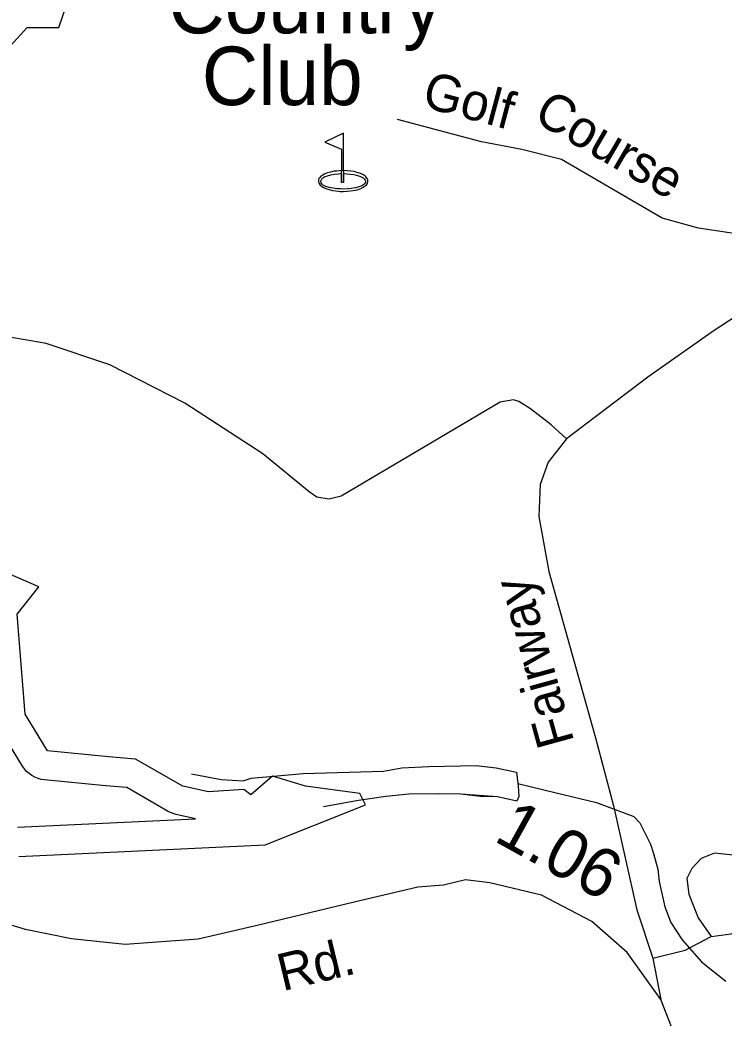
# Model space of a CAD drawing. Extents: x 1473865 to 1648260, y 639067 to 773536.
# Drawn here: x 1511554 to 1513360, y 649038 to 651596 of the extents above; entities that cross this region are included whole.
import ezdxf

# ---------------------------------------------------------------- set-up
doc = ezdxf.new("R2010")
doc.units = 0
for name, color, linetype in [('Exist Cultural Recreational Golf Course CELL', 7, 'Continuous'), ('Exist Hydrographic Buffer Line', 7, 'Continuous'), ('Exist Hydrographic Lake Shore', 7, 'Continuous'), ('Exist Hydrographic Misc Water Feature', 7, 'Continuous'), ('Exist Road Non-System Type 51', 7, 'Continuous'), ('Exist Road Non-System Type 51 Label', 7, 'Continuous'), ('Exist Road Secondary Mileage Hundredths English Label', 7, 'Continuous'), ('Exist Road Secondary Type 51 Attributed', 7, 'Continuous'), ('Exist Road Secondary Type 51 Label', 7, 'Continuous')]:
    doc.layers.add(name, color=color, linetype=linetype)

msp = doc.modelspace()

# ---------------------------------------------------------------- linework, layer by layer
at = {"layer": 'Exist Cultural Recreational Golf Course CELL'}
msp.add_lwpolyline([(1512384.3, 651305.8), (1512336, 651283.4), (1512378.7, 651264.7), (1512378.7, 651210.1), (1512384.3, 651210.1), (1512384.3, 651202.5), (1512384.3, 651179.6), (1512384.3, 651202.5), (1512391.5, 651202), (1512400.8, 651201), (1512410.4, 651199.8), (1512416.9, 651198.5), (1512425.4, 651196), (1512427.5, 651195.3), (1512434.4, 651191.7), (1512438.1, 651188.4), (1512439.7, 651185.5), (1512440.7, 651182.6), (1512440.6, 651181.2), (1512440.2, 651180), (1512439.9, 651179), (1512439.3, 651177.8), (1512436, 651174.2), (1512431.2, 651171.3), (1512422.9, 651168.1), (1512414.8, 651165.9), (1512404, 651164.2), (1512395.7, 651163), (1512383.5, 651162.4), (1512376.6, 651163), (1512367.8, 651163.4), (1512357.7, 651164.8), (1512347.3, 651167.1), (1512338.5, 651169.7), (1512332.5, 651172.3), (1512328.9, 651175.2), (1512326.3, 651178.8), (1512325.5, 651181.9), (1512326.3, 651185.2), (1512328.4, 651188.6), (1512331, 651191.5), (1512333.8, 651193.1), (1512337.3, 651194.9), (1512343.1, 651196.8), (1512351.1, 651199), (1512361.1, 651200.8), (1512370.8, 651202), (1512378.7, 651202.5), (1512378.7, 651210.1), (1512384.3, 651210.1), (1512384.3, 651179.6), (1512378.7, 651179.6), (1512378.7, 651202.5), (1512378.7, 651210.1), (1512366.4, 651209), (1512360.4, 651208.5), (1512351, 651206.3), (1512343.3, 651204.4), (1512334.6, 651201), (1512330.9, 651198.8), (1512326.1, 651195.8), (1512322.9, 651192.5), (1512321, 651190), (1512319.8, 651186.2), (1512319.5, 651183.3), (1512320.3, 651178.8), (1512321.2, 651176.7), (1512323.9, 651173), (1512326.4, 651170.8), (1512330.7, 651167.9), (1512334.3, 651166.1), (1512341.1, 651163.2), (1512346.8, 651161.7), (1512356.1, 651159.5), (1512364.6, 651157.8), (1512375.7, 651156.8), (1512382.9, 651156.5), (1512393.2, 651157.1), (1512400.9, 651157.8), (1512409, 651159.3), (1512418.7, 651161.2), (1512428.2, 651164.4), (1512434.1, 651167.5), (1512439.7, 651170.9), (1512442.7, 651173.9), (1512444.5, 651176.5), (1512445.3, 651178.1), (1512445.8, 651179.4), (1512446.2, 651181.3), (1512446.5, 651183.4), (1512446, 651186.8), (1512444.6, 651190), (1512441.6, 651193.8), (1512439.7, 651195.9), (1512435.2, 651198.9), (1512431.6, 651200.9), (1512425.3, 651203.5), (1512420.9, 651204.7), (1512410.9, 651207.4), (1512402.5, 651208.9), (1512384.3, 651210.1)], close=True, dxfattribs=at)
at = {"layer": 'Exist Hydrographic Buffer Line'}
msp.add_lwpolyline([(1511547.9, 649526.9), (1512004.2, 649548.1), (1511955.1, 649559.3), (1511944.5, 649562.6), (1511934.4, 649567.4), (1511828.1, 649628.5), (1511774.8, 649633.1), (1511774.4, 649633.1), (1511774, 649633.2), (1511617.7, 649648.3), (1511609.1, 649649.6), (1511600.8, 649651.9), (1511592.7, 649655.1), (1511585.1, 649659.3), (1511578.1, 649664.3), (1511571.6, 649670.1), (1511565.9, 649676.6), (1511560.9, 649683.7), (1511503.6, 649777.2)], dxfattribs=at)
at = {"layer": 'Exist Hydrographic Lake Shore'}
for points in [[(1511441, 651433.5), (1511573.3, 651577), (1511654.1, 651577), (1511694.5, 651694.7)], [(1511551.3, 649452), (1512183.4, 649481.4), (1512440.6, 649584.4), (1512425.9, 649613.8), (1512286.3, 649632.2), (1512201.7, 649657.9), (1512146.6, 649610.1), (1512128.6, 649623.4), (1512038.1, 649617.3), (1511971.8, 649632.4), (1511851.1, 649701.8), (1511781.2, 649707.8), (1511624.9, 649722.9), (1511567.6, 649816.4), (1511547.7, 650073.5), (1511602.8, 650143.4), (1511518.3, 650180.1)]]:
    msp.add_lwpolyline(points, dxfattribs=at)
at = {"layer": 'Exist Hydrographic Misc Water Feature'}
for points in [[(1511994.5, 649663.7), (1512070.3, 649649.5), (1512127.1, 649645.9), (1512147.1, 649652.8), (1512280.7, 649664.8), (1512486.1, 649670.3), (1512533.3, 649679.2), (1512602.6, 649682.7), (1512723.9, 649685), (1512775.6, 649679), (1512827.3, 649668), (1512830.9, 649639)], [(1512830.9, 649639), (1512831.6, 649633.3), (1512833.5, 649606.1), (1512828.3, 649593.8), (1512779, 649604.7), (1512734.5, 649605.7), (1512685.2, 649611.7), (1512630.9, 649612.8), (1512551.7, 649612.1), (1512492.3, 649605.9), (1512422.7, 649595.1), (1512332.9, 649579.5)], [(1512830.9, 649639), (1512831.6, 649633.3), (1512833.5, 649606.1), (1512828.3, 649593.8), (1512779, 649604.7), (1512685.2, 649611.7), (1512630.9, 649612.8), (1512551.7, 649612.1), (1512492.3, 649605.9), (1512422.7, 649595.1), (1512332.9, 649579.5)], [(1512830.9, 649639), (1512925.4, 649616.3), (1513033, 649590.3), (1513128.2, 649554.5), (1513144, 649538.2), (1513171, 649483.8), (1513178.6, 649459.6), (1513189.8, 649419.4), (1513193.2, 649387.4), (1513208.1, 649323.2), (1513223.4, 649282.9), (1513252.5, 649238.4), (1513301.5, 649181.5), (1513364.6, 649132.4)]]:
    msp.add_lwpolyline(points, dxfattribs=at)
at = {"layer": 'Exist Road Non-System Type 51'}
for p, q in [((1512737.6, 651283.5), (1512522.6, 651340.9)), ((1513177.3, 649191.6), (1513197.9, 649085.4))]:
    msp.add_line(p, q, dxfattribs=at)
for points in [[(1513640.8, 650977.3), (1513553.4, 651006.7), (1513407.9, 651045.1), (1513294.2, 651062.8), (1513200.6, 651088.3), (1512942.9, 651238.3), (1512841.4, 651263.8), (1512737.6, 651283.5)], [(1513640.8, 650977.3), (1513532.2, 650929.1), (1513334.1, 650800.2), (1513164.2, 650680.8), (1512955.9, 650522.1)], [(1512955.9, 650522.1), (1512916.4, 650558.7), (1512863, 650599.6), (1512833.4, 650618), (1512819.5, 650622.3), (1512785.3, 650616.8), (1512377.7, 650375.3), (1512347.5, 650367.9), (1512315.8, 650373.3), (1512295.9, 650386.5), (1512177.4, 650484.4), (1511977.3, 650613.7), (1511784.8, 650712.6), (1511621.8, 650767.1), (1511444.1, 650797.9)], [(1512955.9, 650522.1), (1512908.9, 650463), (1512888.1, 650405.2), (1512884.9, 650323.2), (1512910.6, 650182.8), (1513030.1, 649756.3), (1513076.3, 649581.6), (1513136.2, 649315), (1513177.3, 649191.6)], [(1513326.2, 649246.6), (1513378.1, 649253.8), (1513428.6, 649276.9), (1513459.6, 649313.1), (1513471.7, 649350.1), (1513474.3, 649390.1), (1513468.4, 649406.2), (1513446.8, 649424.7), (1513383.4, 649455.5), (1513335.5, 649460.3), (1513301.2, 649446.8), (1513276.9, 649421.3), (1513264.3, 649395.5), (1513269.7, 649355.4), (1513292.9, 649295.1), (1513326.2, 649246.6)], [(1513177.3, 649191.6), (1513259.6, 649211.5), (1513326.2, 649246.6)]]:
    msp.add_lwpolyline(points, dxfattribs=at)
at = {"layer": 'Exist Road Secondary Type 51 Attributed'}
msp.add_lwpolyline([(1513271.7, 648894.4), (1513197.9, 649085.4), (1513111.5, 649205.5), (1513020.9, 649285.4), (1512891.4, 649353), (1512759.4, 649384.2), (1512697.1, 649392), (1512640.6, 649378.4), (1512574.4, 649373.5), (1512411.5, 649334.9), (1512162.6, 649274.9), (1512011.5, 649240.1), (1511823.8, 649226.3), (1511686.7, 649240.6), (1511568.8, 649264.9), (1511339.5, 649333.9), (1511214, 649369.8), (1511072.8, 649423.9), (1510974.3, 649458.1)], dxfattribs=at)

# ---------------------------------------------------------------- texts
at = {"layer": 'Exist Cultural Recreational Golf Course CELL'}
for s, p in [('Country', (1511934.7, 651561.9)), ('Club', (1512020.7, 651377.9))]:
    msp.add_text(s, height=150, rotation=0, dxfattribs=at).set_placement(p)
at = {"layer": 'Exist Road Non-System Type 51 Label'}
for s, rotation, p in [('Golf', 345.0581, (1512581.7, 651374.7)), ('Course', 329.7861, (1512867.2, 651339.4)), ('Fairway', 105.4004, (1512976.1, 649746.1))]:
    msp.add_text(s, height=95, rotation=rotation, dxfattribs=at).set_placement(p)
at = {"layer": 'Exist Road Secondary Mileage Hundredths English Label'}
msp.add_text('1.06', height=125, rotation=330.9926, dxfattribs=at).set_placement((1512766.1, 649493.6))
at = {"layer": 'Exist Road Secondary Type 51 Label'}
msp.add_text('Rd.', height=95, rotation=13.555, dxfattribs=at).set_placement((1512227.7, 649106.4))

doc.saveas('drawing.dxf')
